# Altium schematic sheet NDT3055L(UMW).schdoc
size 127 x 101 mm
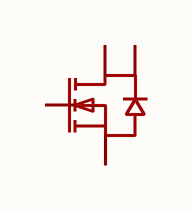
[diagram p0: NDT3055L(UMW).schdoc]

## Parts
Q?  ndt3055l(umw)  [SOT-223-3_L6.5-W3.4-P2.30-LS7.0-BR]  (value not drawn)

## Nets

Not connected (* = marked no-connect by the designer): Q? 1(G) 2(D) 3(S) 4(D)

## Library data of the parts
Q? = ndt3055l(umw): 数量:1个N沟道;漏源电压(Vdss):60V;连续漏极电流(Id):4A;导通电阻(RDS(on)):50mΩ@4.5V;耗散功率(Pd):-;阈值电压(Vgs(th)):1.6V;; Manufacturer: UMW(友台半导体); AddInBom: yes; ModelId: 925194bf9823436183a3e0b978a8d076; ModelName: SOT-223-4P_L6.5-W3.5-H1.6-LS7.0-P2.30; ModelTransform: 279.89794,255.905,0,180,0,0,-3.9385,-0.0005,0; Number: 1个N沟道; Drain to Source Voltage: 60V; Current - Continuous Drain(Id): 4A; Gate Threshold Voltage (Vgs(th)): 1.6V; Gate Charge(Qg): 13nC@40V; Input Capacitance(Ciss): 345pF; Reverse Transfer Capacitance (Crss@Vds): 30pF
